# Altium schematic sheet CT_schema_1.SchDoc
size 519 x 469 mm
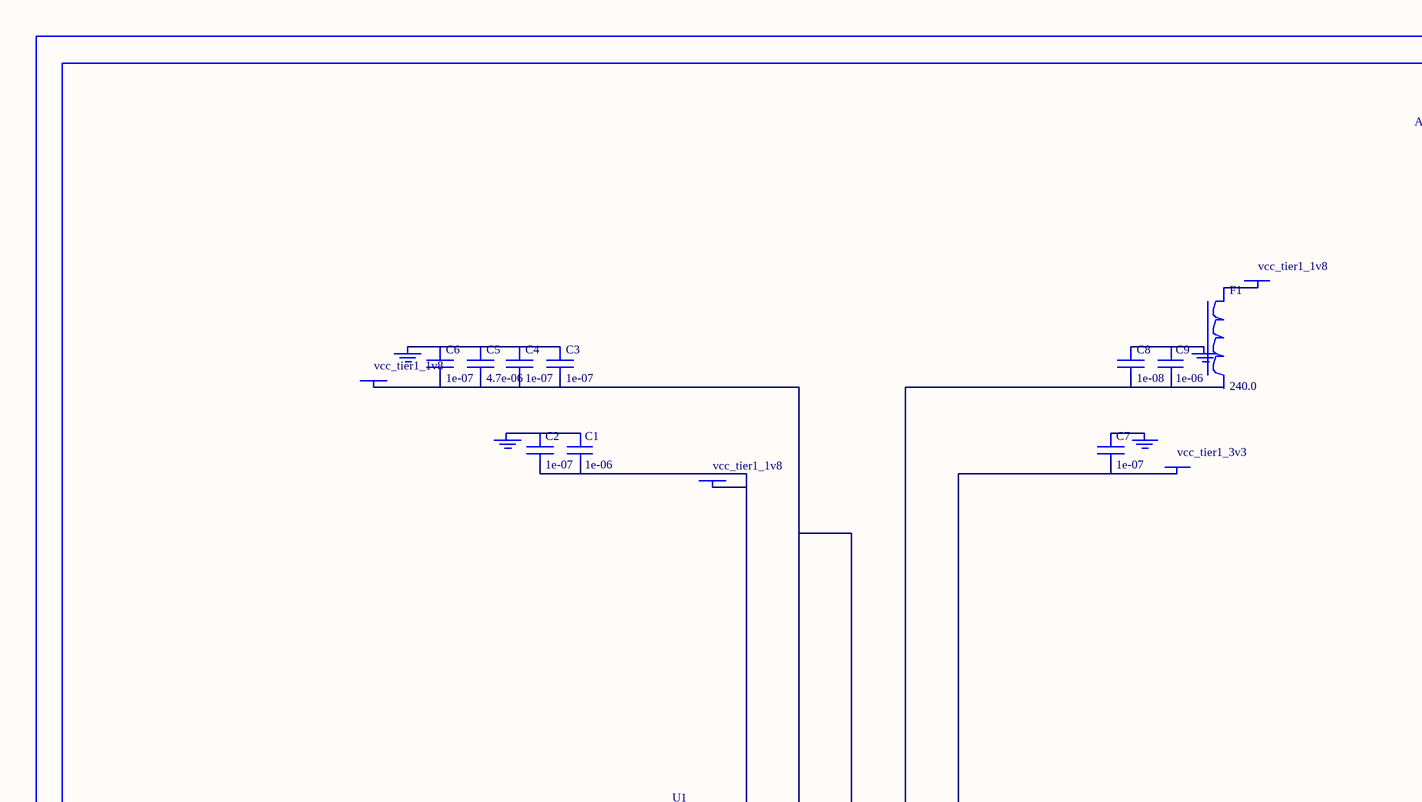
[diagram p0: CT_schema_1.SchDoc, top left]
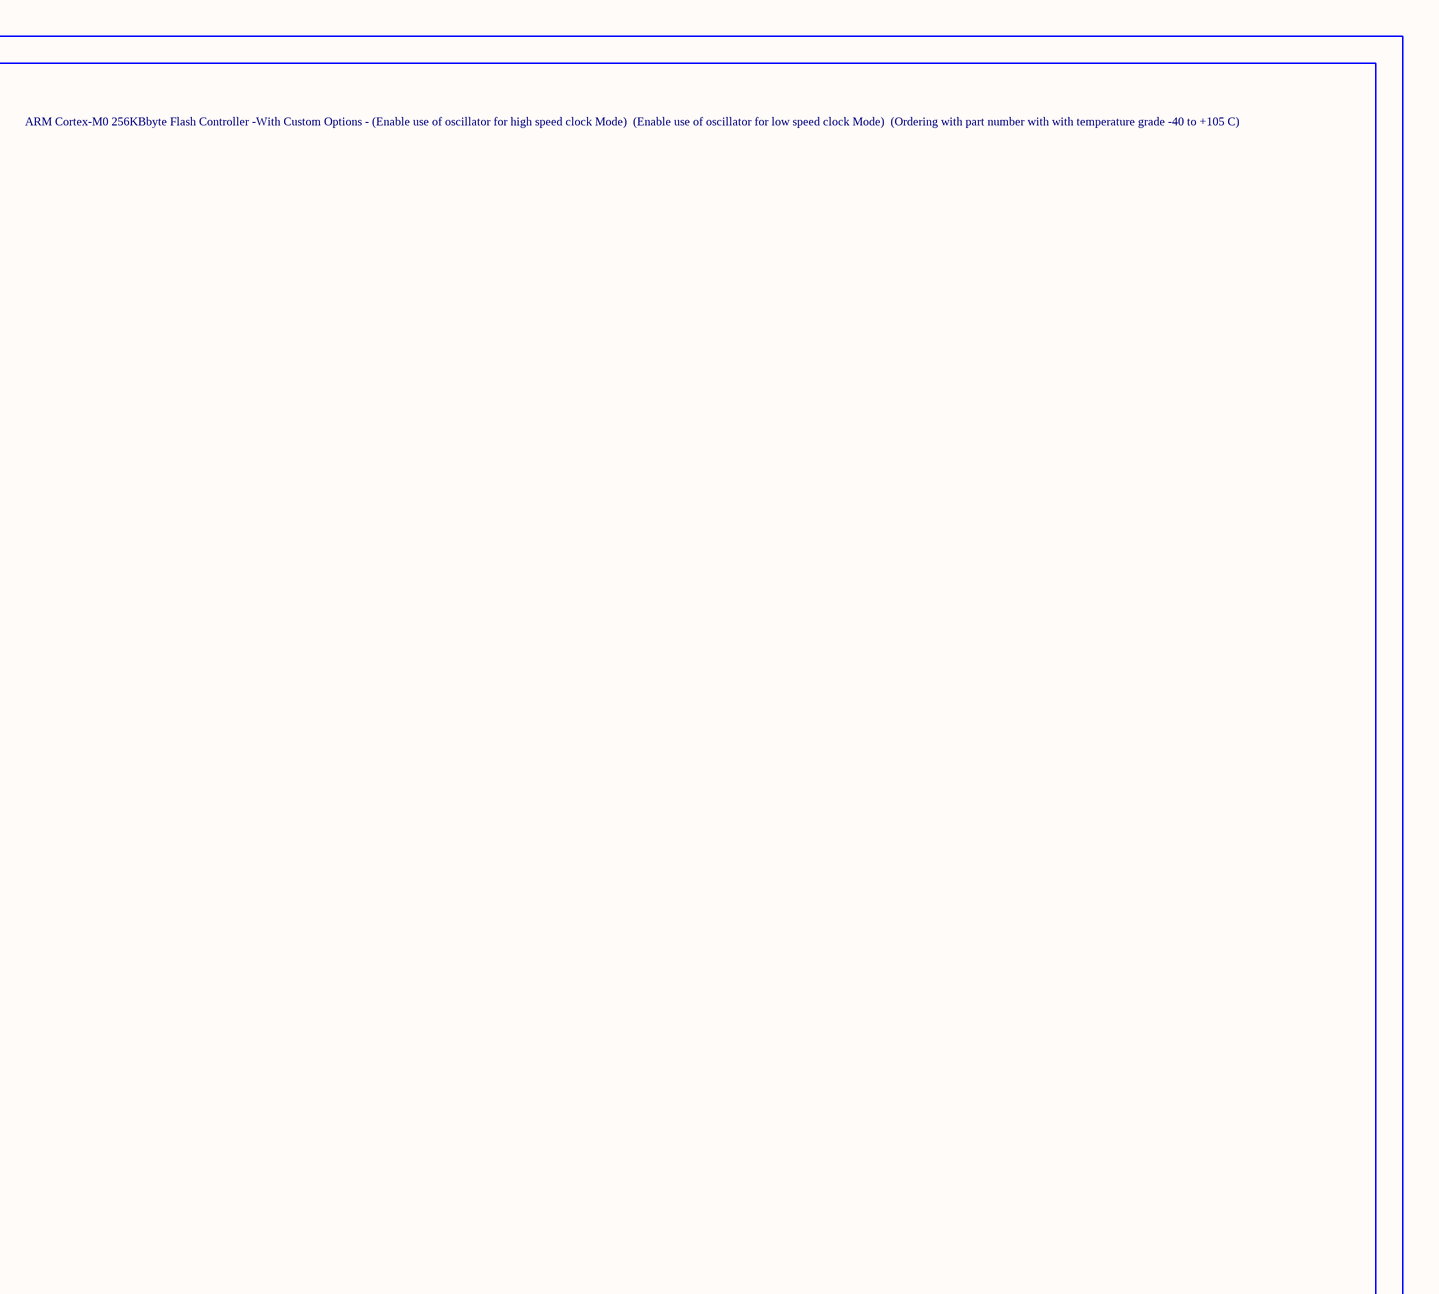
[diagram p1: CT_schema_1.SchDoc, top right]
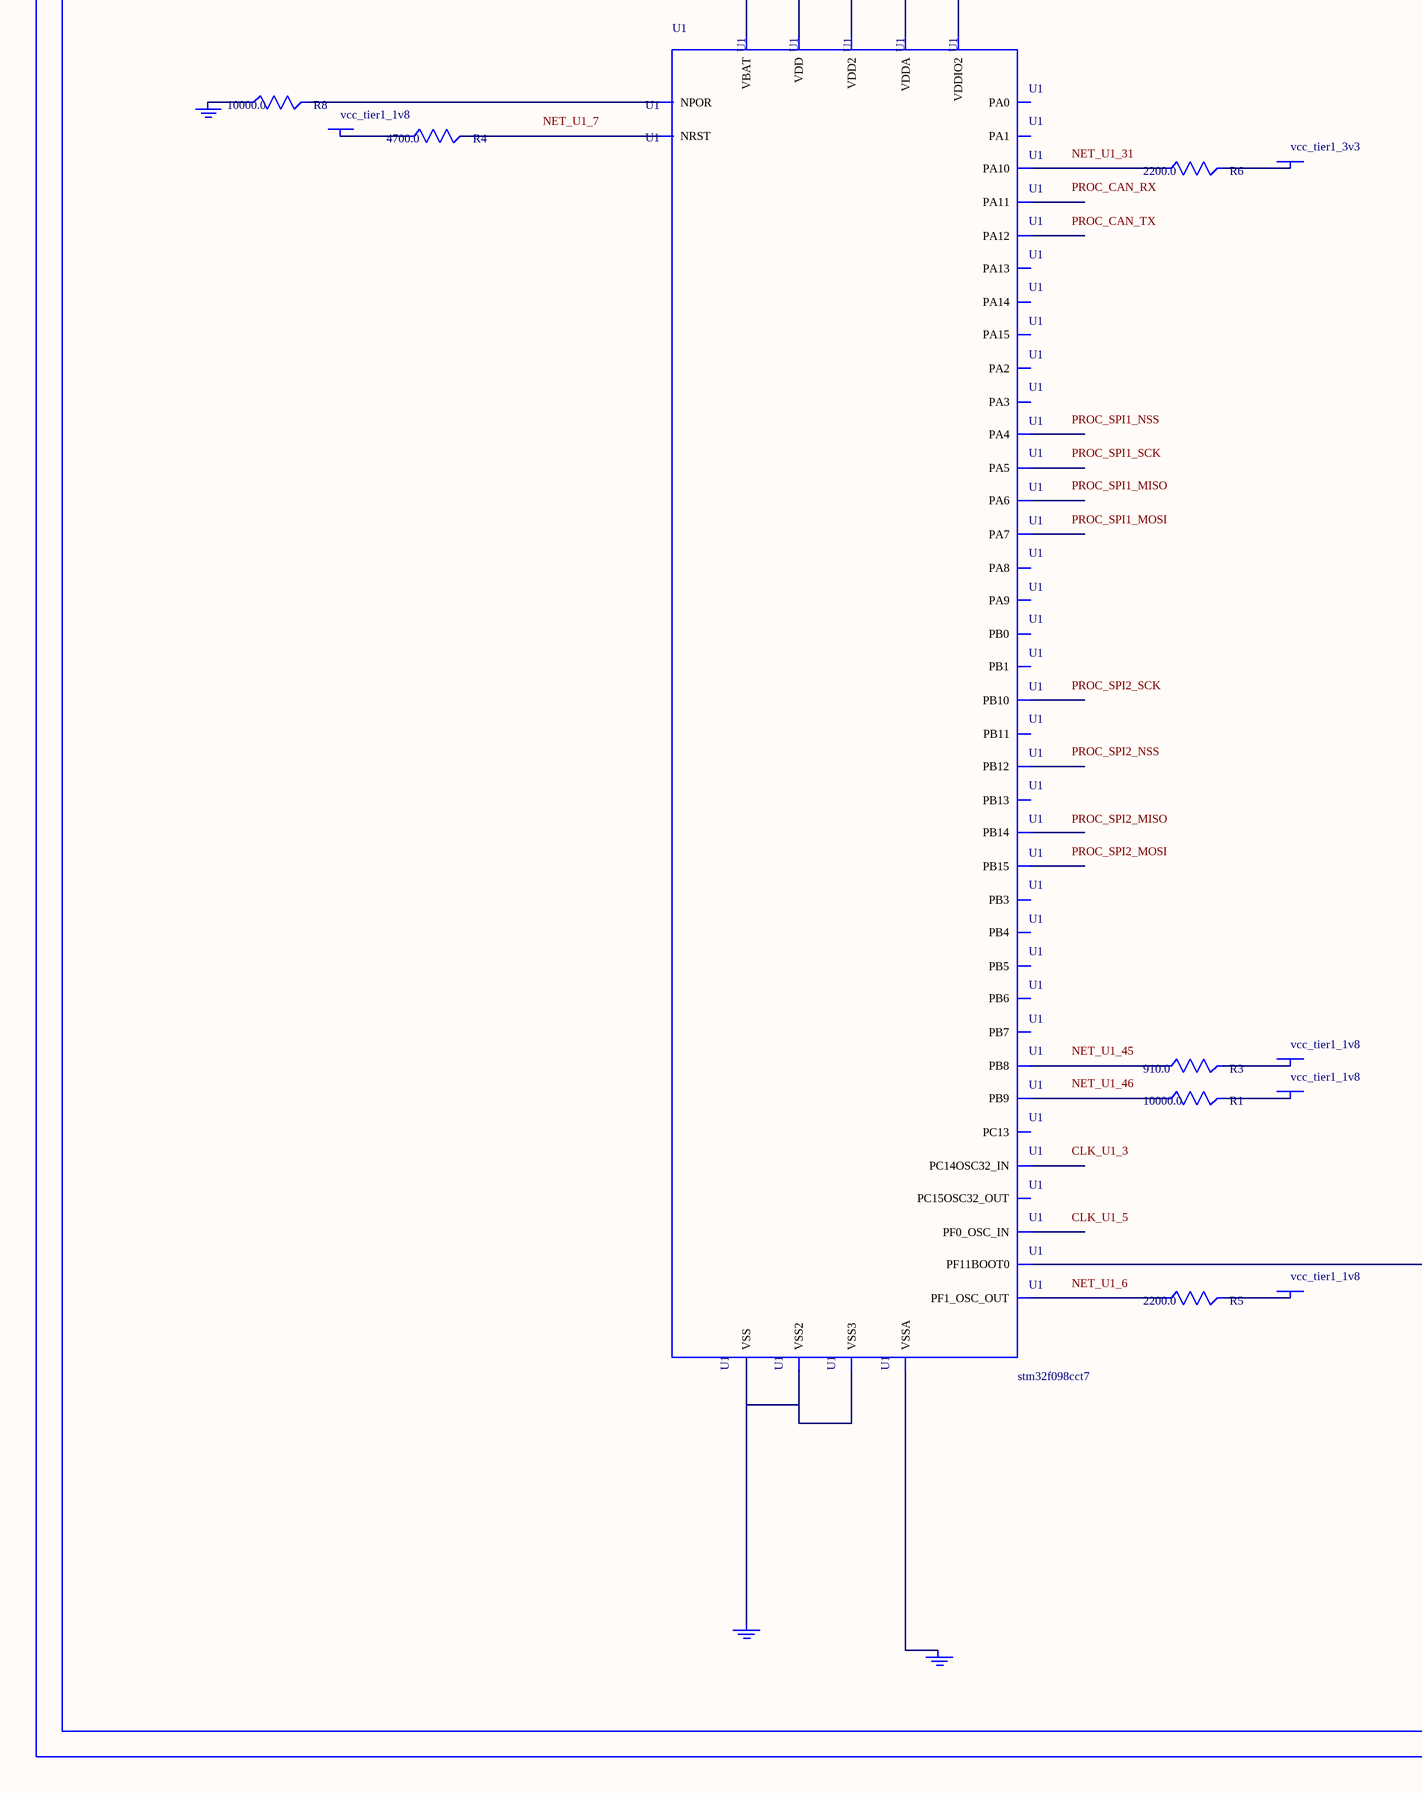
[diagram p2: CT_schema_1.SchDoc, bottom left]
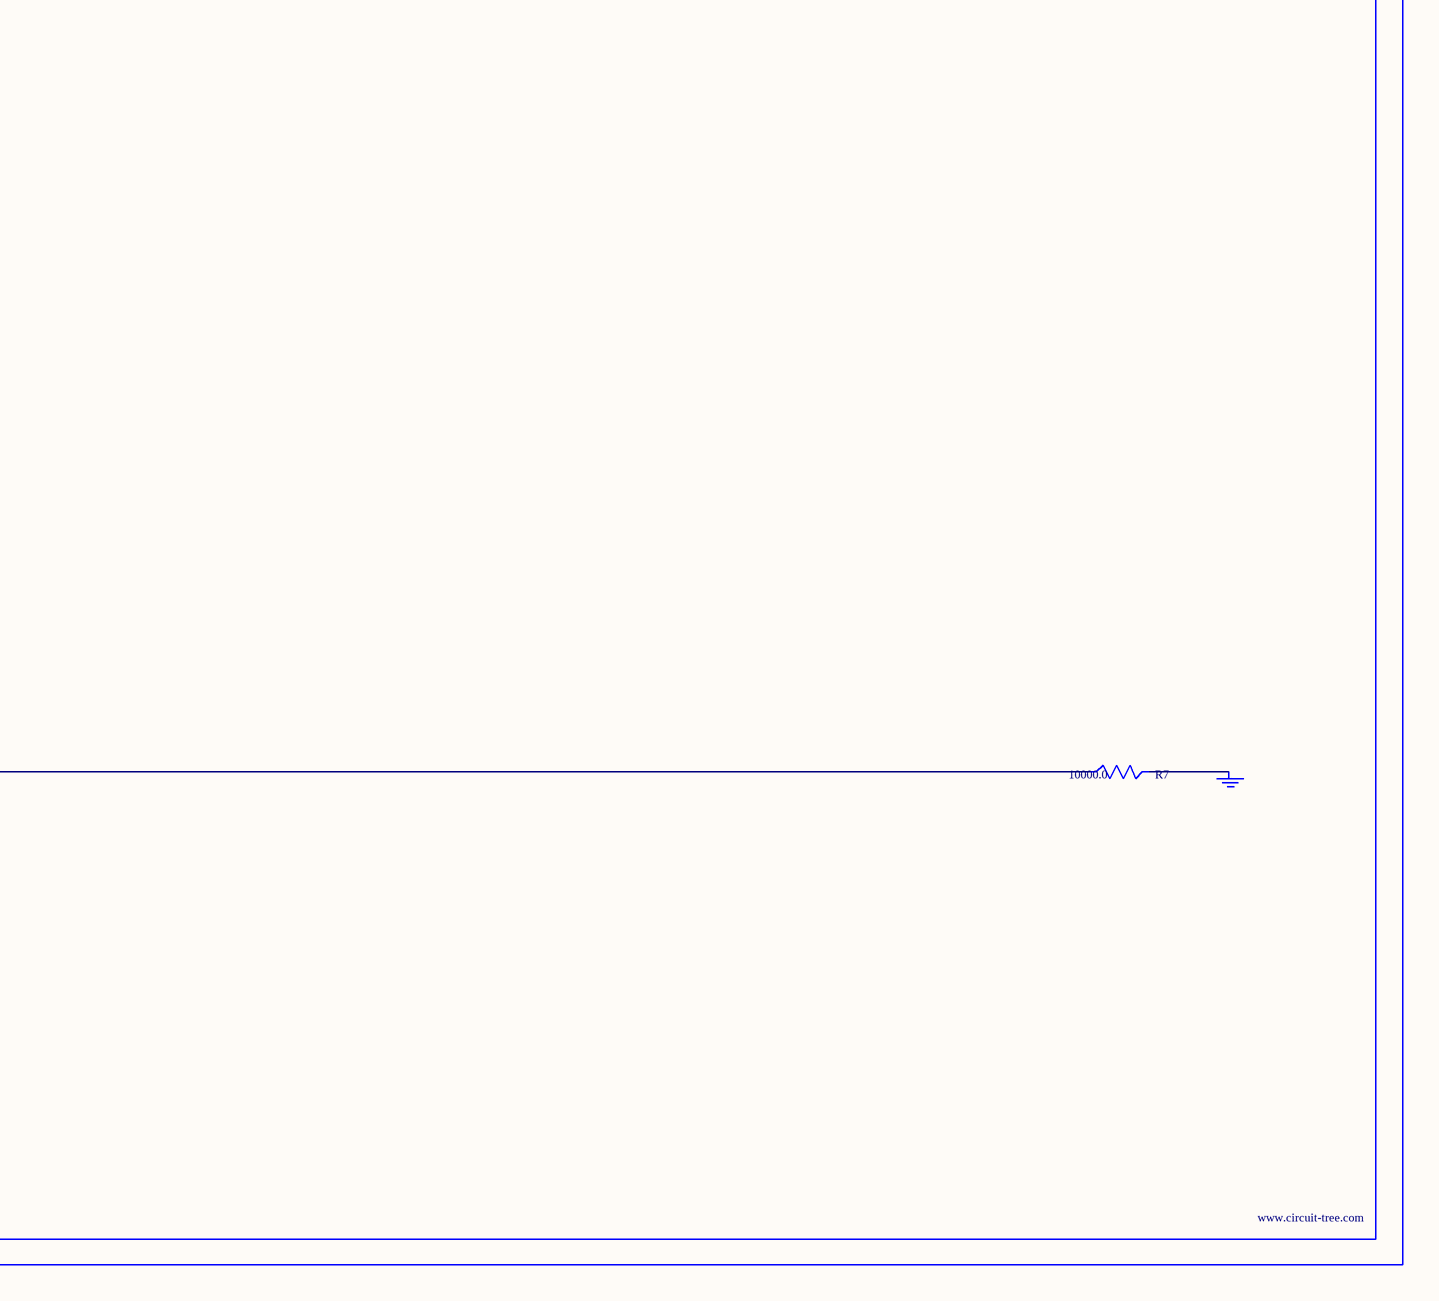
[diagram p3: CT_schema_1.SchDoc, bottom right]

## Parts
BORDER0  (no value)
C1  1e-06  [C0603]
C2  1e-07  [C0603]
C3  1e-07  [C0603]
C4  1e-07  [C0603]
C5  4.7e-06  [C0603]
C6  1e-07  [C0603]
C7  1e-07  [C0603]
C8  1e-08  [C0603]
C9  1e-06  [C0603]
F1  240.0  [L0603]
GND_INSTANCE_0_0  (no value)
GND_INSTANCE_0_1  (no value)
GND_INSTANCE_0_2  (no value)
GND_INSTANCE_0_3  (no value)
GND_INSTANCE_0_4  (no value)
GND_INSTANCE_0_5  (no value)
GND_INSTANCE_0_6  (no value)
GND_INSTANCE_0_7  (no value)
POWER_INSTANCE_0_0  vcc_tier1_1v8
POWER_INSTANCE_0_1  vcc_tier1_1v8
POWER_INSTANCE_0_2  vcc_tier1_1v8
POWER_INSTANCE_0_3  vcc_tier1_3v3
POWER_INSTANCE_0_4  vcc_tier1_1v8
POWER_INSTANCE_0_5  vcc_tier1_1v8
POWER_INSTANCE_0_6  vcc_tier1_3v3
POWER_INSTANCE_0_7  vcc_tier1_1v8
POWER_INSTANCE_0_8  vcc_tier1_1v8
R1  10000.0  [R0603]
R3  910.0  [R0603]
R4  4700.0  [R0603]
R5  2200.0  [R0603]
R6  2200.0  [R0603]
R7  10000.0  [R0603]
R8  10000.0  [R0603]
U1  stm32f098cct7  [LQFP48]

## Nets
NetC1_1: C1.1 C2.1 GND_INSTANCE_0_0.0(GND)
NetC1_2: C1.2 C2.2 POWER_INSTANCE_0_0.0(PWR) U1.1(VBAT)
NetC3_1: C3.1 C4.1 C5.1 C6.1 GND_INSTANCE_0_4.0(GND)
NetC3_2: C3.2 C4.2 C5.2 C6.2 POWER_INSTANCE_0_2.0(PWR) U1.24(VDD) U1.48(VDD2)
NetC7_1: C7.1 GND_INSTANCE_0_5.0(GND)
NetC7_2: C7.2 POWER_INSTANCE_0_3.0(PWR) U1.36(VDDIO2)
NetC8_1: C8.1 C9.1 GND_INSTANCE_0_2.0(GND)
NetC8_2: C8.2 C9.2 U1.9(VDDA)
NetF1_1: F1.1 POWER_INSTANCE_0_1.0(PWR)
NetGND_INSTANCE_0_1_0: GND_INSTANCE_0_1.0(GND) U1.8(VSSA)
NetGND_INSTANCE_0_3_0: GND_INSTANCE_0_3.0(GND) R8.1
NetGND_INSTANCE_0_6_0: GND_INSTANCE_0_6.0(GND) R7.2
NetGND_INSTANCE_0_7_0: GND_INSTANCE_0_7.0(GND) U1.23(VSS) U1.35(VSS2) U1.47(VSS3)
NetPOWER_INSTANCE_0_4_0: POWER_INSTANCE_0_4.0(PWR) R5.2
NetPOWER_INSTANCE_0_5_0: POWER_INSTANCE_0_5.0(PWR) R4.1
NetPOWER_INSTANCE_0_6_0: POWER_INSTANCE_0_6.0(PWR) R6.2
NetPOWER_INSTANCE_0_7_0: POWER_INSTANCE_0_7.0(PWR) R3.2
NetPOWER_INSTANCE_0_8_0: POWER_INSTANCE_0_8.0(PWR) R1.2
NetR1_1: R1.1 U1.46(PB9)
NetR3_1: R3.1 U1.45(PB8)
NetR4_2: R4.2 U1.7(NRST)
NetR5_1: R5.1 U1.6(PF1_OSC_OUT)
NetR6_1: R6.1 U1.31(PA10)
NetR7_1: R7.1 U1.44(PF11BOOT0)
NetR8_2: R8.2 U1.20(NPOR)

Not connected (* = marked no-connect by the designer): F1 2; U1 2(PC13) 3(PC14OSC32_IN) 4(PC15OSC32_OUT) 5(PF0_OSC_IN) 10(PA0) 11(PA1) 12(PA2) 13(PA3) 14(PA4) 15(PA5) 16(PA6) 17(PA7) 18(PB0) 19(PB1) 21(PB10) 22(PB11) 25(PB12) 26(PB13) 27(PB14) 28(PB15) 29(PA8) 30(PA9) 32(PA11) 33(PA12) 34(PA13) 37(PA14) 38(PA15) 39(PB3) 40(PB4) 41(PB5) 42(PB6) 43(PB7)

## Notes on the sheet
- Labels drawn without touching a wire or pin: CLK_U1_3, CLK_U1_5, NET_U1_6, NET_U1_7, NET_U1_31, NET_U1_45, NET_U1_46, PROC_CAN_RX, PROC_CAN_TX, PROC_SPI1_MISO, PROC_SPI1_MOSI, PROC_SPI1_NSS, PROC_SPI1_SCK, PROC_SPI2_MISO, PROC_SPI2_MOSI, PROC_SPI2_NSS, PROC_SPI2_SCK

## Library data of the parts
BORDER0 = BORDER_PAGE0
C1 C9 = C0603C105K3RACTU
C2-C4 C6 C7 = 06035C104K4Z2A
C5 = GRM188R6YA475KE15D
C8 = 06035C103K4Z2A
F1 = Z0603C241ASMST
GND_INSTANCE_0_0-GND_INSTANCE_0_7 = GND
POWER_INSTANCE_0_0-POWER_INSTANCE_0_8 = PWR
R1 R7 R8 = RC0603JR-0710KL
R3 = RC0603JR-07910RL
R4 = RC0603JR-074K7L
R5 R6 = RC0603JR-072K2L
